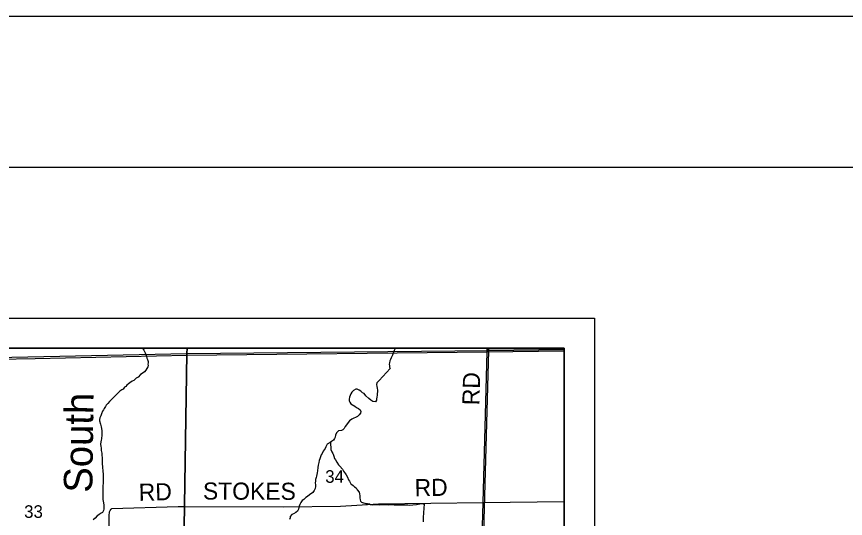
# Model space of a CAD drawing. Extents: x 0 to 34, y 0 to 22.
# Drawn here: x 28.499 to 31.249, y 20.335 to 22 of the extents above; entities that cross this region are included whole.
import ezdxf

# ---------------------------------------------------------------- set-up
doc = ezdxf.new("R2010")
doc.units = 0
for name, color, linetype in [('GM_X_County_Road', 7, 'Continuous'), ('GM_X_County_Road_Text', 7, 'Continuous'), ('GM_X_Minor_River', 7, 'Continuous'), ('GM_X_Minor_River_Text', 7, 'Continuous'), ('GM_X_Section', 7, 'Continuous'), ('GM_X_Section_Text', 7, 'Continuous'), ('GM_X_Township_Road', 7, 'Continuous'), ('GM_X_Township_Road_Text', 7, 'Continuous'), ('SH_Border', 7, 'Continuous'), ('SH_Cut_Line', 7, 'Continuous'), ('SH_Data', 7, 'Continuous')]:
    doc.layers.add(name, color=color, linetype=linetype)

msp = doc.modelspace()

# ---------------------------------------------------------------- linework, layer by layer
at = {"layer": 'GM_X_County_Road'}
msp.add_lwpolyline([(28.801, 19.8664), (28.8036, 20.1477), (28.8064, 20.346), (28.8073, 20.3551), (28.8077, 20.357), (28.8082, 20.3596), (28.8093, 20.3615), (28.8128, 20.3664), (28.8151, 20.3682), (29.0351, 20.3742), (29.0559, 20.3746), (29.0644, 20.8767), (29.0647, 20.9)], dxfattribs=at)
at = {"layer": 'GM_X_Minor_River'}
for points in [[(28.9174, 20.9), (28.921, 20.8936), (28.9239, 20.8886), (28.9258, 20.884), (28.928, 20.8791), (28.9298, 20.8726), (28.9317, 20.8673), (28.9331, 20.8623), (28.9353, 20.8559), (28.9353, 20.8517), (28.9345, 20.8471), (28.9356, 20.8422), (28.9347, 20.8376), (28.9309, 20.8327), (28.9274, 20.8271), (28.9232, 20.8218), (28.9186, 20.8185), (28.9106, 20.8121), (28.9029, 20.8042), (28.8956, 20.8001), (28.8883, 20.793), (28.8822, 20.7904), (28.8753, 20.7847), (28.87, 20.7818), (28.865, 20.7769), (28.8616, 20.7728), (28.857, 20.7701), (28.8524, 20.7641), (28.8478, 20.7615), (28.842, 20.757), (28.8344, 20.7495), (28.8278, 20.7435), (28.8236, 20.7394), (28.8182, 20.7337), (28.8144, 20.7296), (28.8071, 20.7228), (28.8017, 20.7168), (28.7967, 20.7108), (28.7944, 20.7067), (28.7902, 20.7002), (28.7871, 20.6957), (28.7844, 20.6908), (28.7809, 20.6821), (28.7785, 20.6753), (28.7754, 20.6685), (28.7746, 20.6632), (28.7745, 20.6587), (28.7778, 20.6484), (28.7789, 20.6434), (28.7796, 20.6389), (28.7807, 20.6335), (28.7821, 20.6256), (28.7824, 20.6176), (28.782, 20.6123), (28.7815, 20.6077), (28.7811, 20.6035), (28.7807, 20.599), (28.7795, 20.5945), (28.7783, 20.5891), (28.7778, 20.5816), (28.7789, 20.5743), (28.7796, 20.5694), (28.7802, 20.561), (28.782, 20.5519), (28.7823, 20.5451), (28.783, 20.536), (28.7833, 20.5299), (28.7832, 20.5189), (28.7835, 20.5136), (28.7838, 20.5086), (28.7841, 20.5022), (28.7848, 20.4957), (28.7855, 20.4896), (28.7862, 20.4847), (28.7865, 20.4786), (28.7868, 20.4737), (28.7867, 20.4634), (28.7863, 20.4589), (28.7858, 20.4524), (28.7857, 20.4433), (28.7853, 20.4384), (28.785, 20.4141), (28.7856, 20.3981), (28.7863, 20.3924), (28.7884, 20.3803), (28.7887, 20.3753)], [(29.7493, 20.8871), (29.7467, 20.8765), (29.7448, 20.8723), (29.7422, 20.8681), (29.7399, 20.8624), (29.7381, 20.8575), (29.7366, 20.8518), (29.7358, 20.8464), (29.7362, 20.8411), (29.7366, 20.8369), (29.7389, 20.8328), (29.7023, 20.7928)], [(29.7557, 20.9), (29.7549, 20.899), (29.7515, 20.8925), (29.7493, 20.8871)], [(29.7032, 20.7937), (29.6943, 20.7851), (29.6939, 20.7798), (29.695, 20.7729), (29.6957, 20.7672), (29.6963, 20.7611), (29.6963, 20.7551), (29.6958, 20.7501), (29.6954, 20.7444), (29.6946, 20.7372), (29.6937, 20.7323), (29.6929, 20.727), (29.6906, 20.7221), (29.6807, 20.7233), (29.6743, 20.7272), (29.6679, 20.733), (29.6578, 20.7422), (29.6522, 20.7498), (29.6465, 20.7518), (29.6413, 20.7568), (29.6356, 20.761), (29.6296, 20.7638), (29.6243, 20.7638), (29.6167, 20.7601), (29.612, 20.7541), (29.6078, 20.748), (29.6055, 20.7428), (29.6035, 20.7371), (29.6027, 20.731), (29.603, 20.7257), (29.6048, 20.7204), (29.6082, 20.7154), (29.6214, 20.7073), (29.6274, 20.7034), (29.6338, 20.7003), (29.6391, 20.6957), (29.6409, 20.6896), (29.6405, 20.6839), (29.6355, 20.6787), (29.6301, 20.6738), (29.6118, 20.6645), (29.6041, 20.6589), (29.5991, 20.6529), (29.5941, 20.6461), (29.5899, 20.6404), (29.586, 20.634), (29.5822, 20.6287), (29.5772, 20.6265), (29.5673, 20.6259), (29.5604, 20.6195), (29.5573, 20.6119), (29.5557, 20.6047), (29.5538, 20.5998), (29.5507, 20.5945), (29.5446, 20.59), (29.5392, 20.5867), (29.53, 20.5811), (29.5254, 20.5732), (29.523, 20.5667), (29.5169, 20.5588), (29.513, 20.5505), (29.5103, 20.5456), (29.5072, 20.5396), (29.5048, 20.5331), (29.5036, 20.5278), (29.5017, 20.5207), (29.5, 20.5116), (29.4988, 20.5036)], [(29.5402, 20.5873), (29.5421, 20.5636), (29.5448, 20.5557), (29.549, 20.5508), (29.5494, 20.5481), (29.5517, 20.542), (29.5537, 20.5341), (29.5575, 20.5299), (29.5617, 20.5216), (29.5671, 20.5125), (29.5717, 20.5087), (29.5801, 20.4989), (29.5831, 20.4947), (29.5843, 20.4917), (29.5877, 20.4879), (29.59, 20.483), (29.5931, 20.4796), (29.5976, 20.472), (29.6007, 20.4636), (29.6038, 20.4591), (29.6061, 20.4538), (29.6084, 20.4496), (29.6114, 20.4477), (29.616, 20.4447), (29.6206, 20.4402), (29.6255, 20.4364), (29.6286, 20.4326), (29.6297, 20.43), (29.6355, 20.4228), (29.637, 20.4167), (29.6382, 20.4099), (29.6382, 20.403), (29.639, 20.397), (29.6398, 20.3924), (29.644, 20.3894), (29.647, 20.3879), (29.6497, 20.3871), (29.6543, 20.3856), (29.6581, 20.3849), (29.6622, 20.3842), (29.666, 20.3834), (29.6698, 20.3831), (29.674, 20.3819), (29.6812, 20.3801), (29.6877, 20.3809), (29.7029, 20.3806), (29.7055, 20.3809), (29.7169, 20.3818), (29.7215, 20.3814), (29.7344, 20.3807), (29.7374, 20.3811), (29.7519, 20.3804), (29.7682, 20.3805), (29.7712, 20.3801), (29.7845, 20.3806), (29.7917, 20.3802), (29.7978, 20.3799), (29.802, 20.3795), (29.8145, 20.3799), (29.8266, 20.3819), (29.8369, 20.3835), (29.8429, 20.3843), (29.8479, 20.3835), (29.8513, 20.3828), (29.8506, 20.3687), (29.8506, 20.3642), (29.8499, 20.3596), (29.8492, 20.3524), (29.8492, 20.349), (29.8485, 20.3425), (29.8486, 20.3235)], [(29.4988, 20.5036), (29.4972, 20.493), (29.496, 20.4866), (29.4951, 20.4809), (29.4943, 20.4759), (29.4927, 20.4706), (29.4911, 20.4638), (29.4907, 20.4585), (29.4903, 20.4528), (29.4906, 20.4464), (29.4905, 20.4411), (29.4893, 20.4346), (29.4869, 20.4278), (29.4819, 20.421), (29.4712, 20.4132), (29.4647, 20.4083), (29.4586, 20.405), (29.4517, 20.3974), (29.4463, 20.3945), (29.4425, 20.3884), (29.439, 20.3813), (29.4367, 20.3763), (29.4343, 20.3654), (29.4315, 20.3597), (29.4262, 20.3552), (29.4174, 20.3504), (29.4121, 20.3478), (29.4074, 20.3421), (29.4066, 20.3372), (29.4047, 20.3315)], [(28.7887, 20.3753), (28.7887, 20.3711), (28.7886, 20.3662), (28.7871, 20.3613), (28.7836, 20.3552), (28.7778, 20.3515), (28.7717, 20.3474), (28.7664, 20.3433), (28.7598, 20.3365), (28.7526, 20.3309)]]:
    msp.add_lwpolyline(points, dxfattribs=at)
at = {"layer": 'GM_X_Section'}
for points in [[(29.0645, 20.8822), (29.0488, 19.8748), (29.0105, 19.8743), (28.0523, 19.8602), (28.0611, 20.8611)], [(29.0649, 20.9), (28.0617, 20.9), (28.0611, 20.8611), (29.0645, 20.8822)], [(30.0649, 20.8926), (30.0369, 19.8872), (30.0112, 19.8862), (29.0488, 19.8748), (29.0645, 20.8822)], [(30.065, 20.9), (29.0649, 20.9), (29.0645, 20.8822), (30.0649, 20.8926)], [(30.3167, 19.8909), (30.3167, 20.8955), (30.0649, 20.8926), (30.0369, 19.8872)], [(30.3167, 20.8955), (30.3167, 20.9), (30.065, 20.9), (30.0649, 20.8926)]]:
    msp.add_lwpolyline(points, close=True, dxfattribs=at)
at = {"layer": 'GM_X_Township_Road'}
for p, q in [((28.5606, 20.8662), (29.0644, 20.8767)), ((29.0644, 20.8767), (30.0607, 20.8881)), ((30.0474, 20.3884), (30.0607, 20.8881)), ((30.0607, 20.8881), (30.061, 20.9)), ((30.0607, 20.8881), (30.3167, 20.8916)), ((28.0568, 20.8556), (28.5606, 20.8662)), ((30.0335, 19.8831), (30.0474, 20.3884)), ((30.0474, 20.3884), (30.3167, 20.3918))]:
    msp.add_line(p, q, dxfattribs=at)
msp.add_lwpolyline([(29.0559, 20.3746), (29.3847, 20.3735), (29.5734, 20.3755), (29.7003, 20.3841), (30.0474, 20.3884)], dxfattribs=at)
at = {"layer": 'SH_Border'}
msp.add_lwpolyline([(1.5, 21.5), (33.5, 21.5), (33.5, 0.5), (1.5, 0.5)], close=True, dxfattribs=at)
at = {"layer": 'SH_Cut_Line'}
msp.add_lwpolyline([(0, 0), (34, 0), (34, 22), (0, 22)], close=True, dxfattribs=at)
at = {"layer": 'SH_Data'}
for points in [[(23.4167, 21), (30.4167, 21), (30.4167, 14), (23.4167, 14)], [(23.5167, 20.9), (30.3167, 20.9), (30.3167, 14.1), (23.5167, 14.1)]]:
    msp.add_lwpolyline(points, close=True, dxfattribs=at)

# ---------------------------------------------------------------- texts
at = {"layer": 'GM_X_County_Road_Text'}
msp.add_text('RD', height=0.05682, rotation=1.4816, dxfattribs=at).set_placement((28.9051, 20.3933))
at = {"layer": 'GM_X_Minor_River_Text'}
msp.add_text('South', height=0.09476, rotation=89.2649, dxfattribs=at).set_placement((28.7502, 20.4201))
at = {"layer": 'GM_X_Section_Text'}
for s, p in [('34', (29.5232, 20.4533)), ('33', (28.524, 20.337))]:
    msp.add_text(s, height=0.04186, rotation=0, dxfattribs=at).set_placement(p)
at = {"layer": 'GM_X_Township_Road_Text'}
for s, rotation, p in [('RD', 88.5193, (30.0349, 20.71)), ('RD', 0.9881, (29.8203, 20.4085)), ('STOKES', 359.8182, (29.1174, 20.3977))]:
    msp.add_text(s, height=0.05682, rotation=rotation, dxfattribs=at).set_placement(p)

doc.saveas('drawing.dxf')
